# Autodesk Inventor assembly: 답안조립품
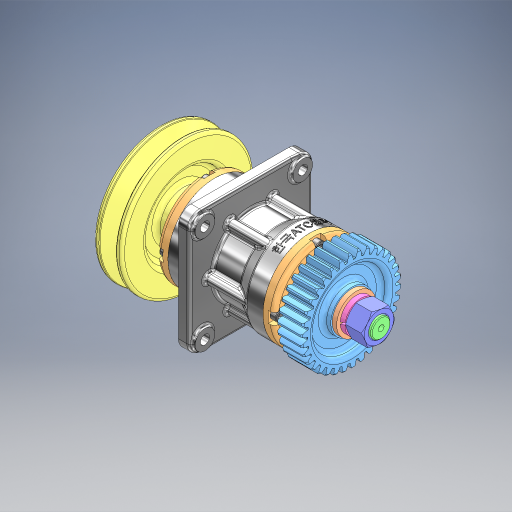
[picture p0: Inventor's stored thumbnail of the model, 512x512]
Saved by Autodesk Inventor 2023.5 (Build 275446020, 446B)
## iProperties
Created: 2025-08
Part Number: 답안조립품
Document SubType Name: Assembly
Designer: 1강의실14
Author: 1강의실14
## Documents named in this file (14)
- C:\Users\1강의실14\Desktop\750803V1001\답안조립품.iam
- C:\Users\1강의실14\Desktop\750803V1001\본체.ipt
- C:\Users\1강의실14\Desktop\750803V1001\깊은 홈 볼 베어링 6005\깊은 홈 볼 베어링 6005.ipt
- C:\Users\1강의실14\Desktop\750803V1001\축\축.ipt
- C:\Users\1강의실14\Desktop\750803V1001\커버\커버.ipt
- C:\Users\1강의실14\Desktop\750803V1001\오일 실 25 38 5\오일 실 25 38 5.ipt
- C:\Users\1강의실14\Desktop\750803V1001\6각 구멍붙이 볼트 M4x10\6각 구멍붙이 볼트 M4x10.ipt
- C:\Users\1강의실14\Desktop\750803V1001\평행 키 6x6x14\평행 키 6x6x14.ipt
- C:\Users\1강의실14\Desktop\750803V1001\평행 키 6x6x18\평행 키 6x6x18.ipt
- C:\Users\1강의실14\Desktop\750803V1001\V 벨트 풀리\V 벨트 풀리.ipt
- C:\Users\1강의실14\Desktop\750803V1001\스퍼기어\스퍼기어.ipt
- C:\Users\1강의실14\Desktop\750803V1001\평 와셔 M14\평 와셔 M14.ipt
- C:\Users\1강의실14\Desktop\750803V1001\스프링 와셔 M14\스프링 와셔 M14.ipt
- C:\Users\1강의실14\Desktop\750803V1001\6각 너트 M14x1\6각 너트 M14x1.ipt
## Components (11 placed, 3 different names)
1. V 벨트 풀리:2
2. 6각 너트 M14x1:1
3. 6각 너트 M14x1:2
4. 6각 구멍붙이 볼트 M4x10:2
5. 6각 구멍붙이 볼트 M4x10:3
6. 6각 구멍붙이 볼트 M4x10:4
7. 6각 구멍붙이 볼트 M4x10:5
8. 6각 구멍붙이 볼트 M4x10:1
9. 6각 구멍붙이 볼트 M4x10:6
10. 6각 구멍붙이 볼트 M4x10:7
11. 6각 구멍붙이 볼트 M4x10:8
